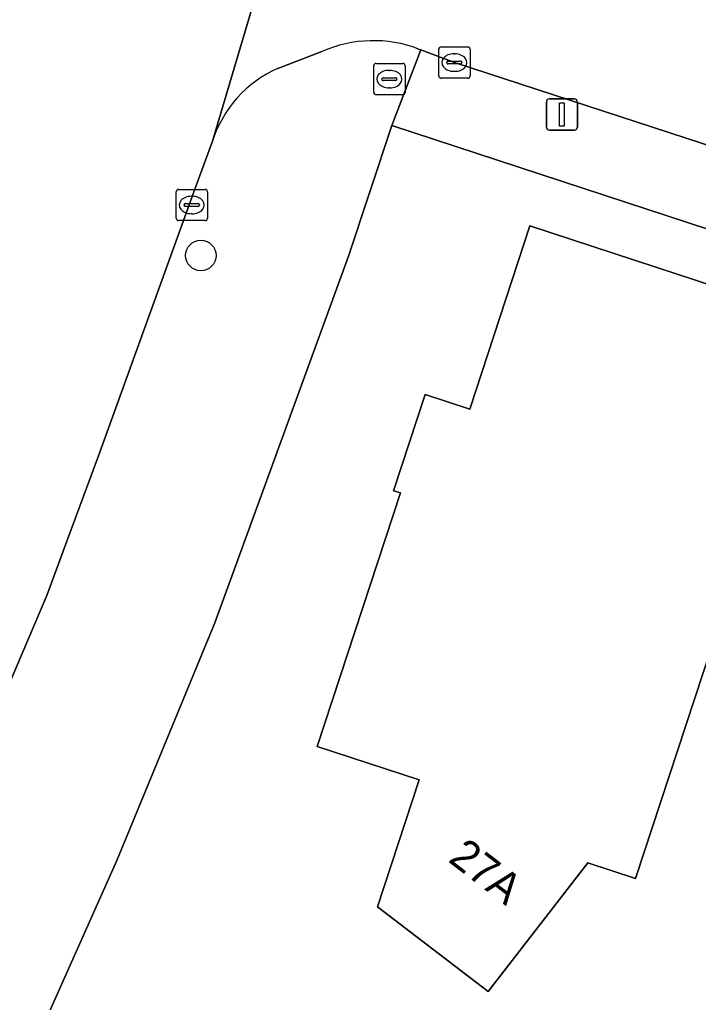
# Model space of a CAD drawing. Extents: x 162803 to 163818, y 381639 to 382475.
# Drawn here: x 163146.73 to 163168.45, y 382007.24 to 382038.7 of the extents above; entities that cross this region are included whole.
import ezdxf

# ---------------------------------------------------------------- set-up
doc = ezdxf.new("R2010")
doc.units = 0
for name, color, linetype in [('IMGEO_Boom', 7, 'Continuous'), ('IMGEO_Brandkraan', 7, 'Continuous'), ('IMGEO_Erf', 7, 'Continuous'), ('IMGEO_Kolk', 7, 'Continuous'), ('IMGEO_Lichtmast', 7, 'Continuous'), ('IMGEO_Pand', 7, 'Continuous'), ('IMGEO_Pand_nummerreeks', 7, 'Continuous'), ('IMGEO_Rijbaan_lokaal_open', 7, 'Continuous'), ('IMGEO_Voetpad_open', 7, 'Continuous')]:
    doc.layers.add(name, color=color, linetype=linetype)

msp = doc.modelspace()

# ---------------------------------------------------------------- linework, layer by layer
at = {"layer": 'IMGEO_Boom'}
msp.add_circle((163152.532, 382031.152), 0.489, dxfattribs=at)
at = {"layer": 'IMGEO_Brandkraan'}
for p, q in [((163158.14, 382037.299), (163158.992, 382037.299)), ((163158.065, 382036.373), (163158.065, 382037.225)), ((163158.553, 382037.079), (163158.578, 382037.079)), ((163159.066, 382037.225), (163159.066, 382036.373)), ((163158.324, 382036.793), (163158.324, 382036.805)), ((163158.762, 382036.756), (163158.364, 382036.756)), ((163158.367, 382036.842), (163158.765, 382036.842)), ((163158.808, 382036.805), (163158.808, 382036.793)), ((163158.992, 382036.299), (163158.14, 382036.299)), ((163158.576, 382036.519), (163158.551, 382036.519))]:
    msp.add_line(p, q, dxfattribs=at)
for points in [[(163158.14, 382037.299), (163158.992, 382037.299)], [(163158.065, 382036.373), (163158.065, 382037.225)], [(163159.066, 382037.225), (163159.066, 382036.373)], [(163158.992, 382036.299), (163158.14, 382036.299)]]:
    msp.add_lwpolyline(points, dxfattribs=at)
for centre, radius, start, end in [((163158.142, 382037.223), 0.0765, 91.552, 178.448), ((163158.142, 382037.223), 0.0765, 91.552, 178.448), ((163158.99, 382037.223), 0.0765, 1.552, 88.448), ((163158.99, 382037.223), 0.0765, 1.552, 88.448), ((163158.364, 382036.802), 0.0403, 85.8775, 175.7526), ((163158.361, 382036.792), 0.0366, 178.938, 274.7102), ((163158.765, 382036.799), 0.043, 264.8664, 352.4533), ((163158.769, 382036.804), 0.0386, 1.7309, 96.639), ((163158.142, 382036.375), 0.0765, 181.552, 268.448), ((163158.142, 382036.375), 0.0765, 181.552, 268.448), ((163158.99, 382036.375), 0.0765, 271.552, 358.448), ((163158.99, 382036.375), 0.0765, 271.552, 358.448)]:
    msp.add_arc(centre, radius, start, end, dxfattribs=at)
for centre, major_axis, ratio, start_param, end_param in [((163158.552, 382036.799), (-0.387, 0.002), 0.722429, 4.712389, 7.853982), ((163158.577, 382036.799), (-0.39, 0.002), 0.717154, 1.570796, 4.712389)]:
    msp.add_ellipse(centre, major_axis=major_axis, ratio=ratio, start_param=start_param, end_param=end_param, dxfattribs=at)
at = {"layer": 'IMGEO_Erf'}
for points in [[(163181.042, 382027.961), (163158.644, 382035.308), (163157.261, 382031.134), (163152.976, 382019.388), (163149.842, 382011.784), (163147.249, 382005.964), (163155.874, 382000), (163183.007, 381981.238)], [(163169.402, 382020.229), (163166.441, 382011.205), (163164.916, 382011.705), (163161.724, 382007.587), (163158.189, 382010.298), (163159.522, 382014.364), (163156.254, 382015.436), (163158.916, 382023.552), (163158.7, 382023.623), (163159.709, 382026.7), (163161.135, 382026.232), (163163.058, 382032.097), (163180.491, 382026.378)]]:
    msp.add_lwpolyline(points, dxfattribs=at)
at = {"layer": 'IMGEO_Kolk'}
for p, q in [((163160.144, 382036.901), (163160.144, 382037.753)), ((163160.219, 382037.827), (163161.071, 382037.827)), ((163160.632, 382037.607), (163160.657, 382037.607)), ((163161.145, 382037.753), (163161.145, 382036.901)), ((163160.403, 382037.321), (163160.403, 382037.333)), ((163160.841, 382037.284), (163160.443, 382037.284)), ((163160.446, 382037.37), (163160.844, 382037.37)), ((163160.887, 382037.333), (163160.887, 382037.321)), ((163160.655, 382037.047), (163160.63, 382037.047)), ((163161.071, 382036.827), (163160.219, 382036.827)), ((163151.741, 382032.342), (163151.741, 382033.194)), ((163151.816, 382033.268), (163152.668, 382033.268)), ((163152.742, 382033.194), (163152.742, 382032.342)), ((163152.229, 382033.048), (163152.254, 382033.048)), ((163152, 382032.762), (163152, 382032.774)), ((163152.438, 382032.725), (163152.04, 382032.725)), ((163152.043, 382032.811), (163152.441, 382032.811)), ((163152.484, 382032.774), (163152.484, 382032.762)), ((163152.668, 382032.268), (163151.816, 382032.268)), ((163152.252, 382032.488), (163152.227, 382032.488))]:
    msp.add_line(p, q, dxfattribs=at)
for points in [[(163160.144, 382036.901), (163160.144, 382037.753)], [(163160.219, 382037.827), (163161.071, 382037.827)], [(163161.145, 382037.753), (163161.145, 382036.901)], [(163161.071, 382036.827), (163160.219, 382036.827)], [(163151.741, 382032.342), (163151.741, 382033.194)], [(163151.816, 382033.268), (163152.668, 382033.268)], [(163152.742, 382033.194), (163152.742, 382032.342)], [(163152.668, 382032.268), (163151.816, 382032.268)]]:
    msp.add_lwpolyline(points, dxfattribs=at)
for centre, radius, start, end in [((163160.221, 382037.751), 0.0765, 91.552, 178.448), ((163160.221, 382037.751), 0.0765, 91.552, 178.448), ((163161.069, 382037.751), 0.0765, 1.552, 88.448), ((163161.069, 382037.751), 0.0765, 1.552, 88.448), ((163160.443, 382037.33), 0.0403, 85.8775, 175.7526), ((163160.44, 382037.32), 0.0366, 178.938, 274.7102), ((163160.844, 382037.327), 0.043, 264.8664, 352.4533), ((163160.848, 382037.332), 0.0386, 1.7309, 96.639), ((163160.221, 382036.903), 0.0765, 181.552, 268.448), ((163160.221, 382036.903), 0.0765, 181.552, 268.448), ((163161.069, 382036.903), 0.0765, 271.552, 358.448), ((163161.069, 382036.903), 0.0765, 271.552, 358.448), ((163151.818, 382033.192), 0.0765, 91.552, 178.448), ((163151.818, 382033.192), 0.0765, 91.552, 178.448), ((163152.666, 382033.192), 0.0765, 1.552, 88.448), ((163152.666, 382033.192), 0.0765, 1.552, 88.448), ((163152.04, 382032.771), 0.0403, 85.8775, 175.7526), ((163152.037, 382032.761), 0.0366, 178.938, 274.7102), ((163152.441, 382032.768), 0.043, 264.8664, 352.4533), ((163152.445, 382032.773), 0.0386, 1.7309, 96.639), ((163151.818, 382032.344), 0.0765, 181.552, 268.448), ((163151.818, 382032.344), 0.0765, 181.552, 268.448), ((163152.666, 382032.344), 0.0765, 271.552, 358.448), ((163152.666, 382032.344), 0.0765, 271.552, 358.448)]:
    msp.add_arc(centre, radius, start, end, dxfattribs=at)
for centre, major_axis, ratio, start_param, end_param in [((163160.631, 382037.327), (-0.387, 0.002), 0.722429, 4.712389, 7.853982), ((163160.656, 382037.327), (-0.39, 0.002), 0.717154, 1.570796, 4.712389), ((163152.228, 382032.768), (-0.387, 0.002), 0.722429, 4.712389, 7.853982), ((163152.253, 382032.768), (-0.39, 0.002), 0.717154, 1.570796, 4.712389)]:
    msp.add_ellipse(centre, major_axis=major_axis, ratio=ratio, start_param=start_param, end_param=end_param, dxfattribs=at)
at = {"layer": 'IMGEO_Lichtmast'}
for p, q in [((163163.589, 382035.265), (163163.589, 382036.065)), ((163163.589, 382036.065), (163163.589, 382035.265)), ((163163.689, 382036.165), (163164.479, 382036.165)), ((163164.479, 382036.165), (163163.689, 382036.165)), ((163164.579, 382036.065), (163164.579, 382035.265)), ((163164.579, 382035.265), (163164.579, 382036.065)), ((163164.479, 382035.165), (163163.689, 382035.165)), ((163163.689, 382035.165), (163164.479, 382035.165))]:
    msp.add_line(p, q, dxfattribs=at)
msp.add_lwpolyline([(163164.009, 382036.04), (163164.159, 382036.04), (163164.159, 382035.29), (163164.009, 382035.29), (163164.009, 382036.04)], dxfattribs=at)
for centre, start, end in [((163163.689, 382036.065), 90, 180), ((163163.689, 382036.065), 90, 180), ((163164.479, 382036.065), 0, 90), ((163164.479, 382036.065), 360, 90), ((163163.689, 382035.265), 180, 270), ((163163.689, 382035.265), 180, 270), ((163164.479, 382035.265), 270, 0), ((163164.479, 382035.265), 270, 0)]:
    msp.add_arc(centre, 0.1, start, end, dxfattribs=at)
at = {"layer": 'IMGEO_Pand'}
msp.add_lwpolyline([(163180.491, 382026.378), (163163.058, 382032.097), (163161.135, 382026.232), (163159.709, 382026.7), (163158.7, 382023.623), (163158.916, 382023.552), (163156.254, 382015.436), (163159.522, 382014.364), (163158.189, 382010.298), (163161.724, 382007.587), (163164.916, 382011.705), (163166.441, 382011.205), (163169.402, 382020.229), (163177.593, 382017.542), (163178.496, 382020.295)], close=True, dxfattribs=at)
at = {"layer": 'IMGEO_Rijbaan_lokaal_open'}
for points in [[(163139.46, 382016.281), (163138.285, 382013.516), (163143.832, 382011.14), (163146.235, 382017.05), (163147.599, 382020.265), (163148.28, 382022.097), (163149.261, 382024.736), (163152.342, 382033.275), (163152.905, 382034.812), (163157.77, 382051.207)], [(163157.77, 382051.207), (163152.905, 382034.812)], [(163159.5, 382037.762), (163159.567, 382037.737), (163160.645, 382037.327), (163176.484, 382032.15), (163186.097, 382029.003), (163194.957, 382026.049), (163197.135, 382032.623), (163161.734, 382044.254)], [(163154.99, 382037.142), (163156.405, 382037.682)]]:
    msp.add_lwpolyline(points, dxfattribs=at)
for centre, radius, start, end in [((163158.05, 382033.962), 4.067, 69.1109, 113.8505), ((163156.55, 382033.648), 3.827, 114.0648, 162.2877)]:
    msp.add_arc(centre, radius, start, end, dxfattribs=at)
at = {"layer": 'IMGEO_Voetpad_open'}
for points in [[(163156.405, 382037.682), (163154.99, 382037.142)], [(163157.261, 382031.134), (163158.644, 382035.308), (163159.567, 382037.737), (163159.5, 382037.762)], [(163176.484, 382032.15), (163160.645, 382037.327), (163159.567, 382037.737), (163158.644, 382035.308), (163181.042, 382027.961)], [(163152.905, 382034.812), (163152.342, 382033.275), (163149.261, 382024.736), (163148.28, 382022.097), (163147.599, 382020.265), (163146.235, 382017.05), (163143.832, 382011.14), (163142.874, 382008.938), (163147.249, 382005.964), (163149.842, 382011.784), (163152.976, 382019.388), (163157.261, 382031.134)]]:
    msp.add_lwpolyline(points, dxfattribs=at)
for centre, radius, start, end in [((163158.05, 382033.962), 4.067, 69.1109, 113.8505), ((163156.55, 382033.648), 3.827, 114.0648, 162.2877)]:
    msp.add_arc(centre, radius, start, end, dxfattribs=at)

# ---------------------------------------------------------------- texts
at = {"layer": 'IMGEO_Pand_nummerreeks'}
msp.add_text('27A', height=1, rotation=322.5171, dxfattribs=at).set_placement((163160.413, 382011.768))

doc.saveas('drawing.dxf')
